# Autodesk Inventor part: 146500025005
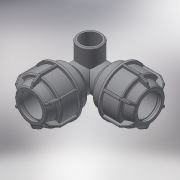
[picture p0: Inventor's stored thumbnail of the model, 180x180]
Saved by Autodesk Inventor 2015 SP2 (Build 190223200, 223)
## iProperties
Created: 2017-08
Part Number: 146500025005
Material: Generic
Description: PLASSON L.14 CORNER TEE ELBOW FEMALE (SILVER) 25-1/2"-25
Document SubType Name: Modeling
Designer: KIM
Density: 1 g/cm^3
Appearance: Default
Author: KIM
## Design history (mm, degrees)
derived "146500.ipt"
feature "Solid1::146500.ipt"
feature "Solid2::146500.ipt"
feature "Solid3::146500.ipt"
tag "TaggingFeature1"
body "Solid1"
body "Solid2"
body "Solid3"
other parameters: "d1" = 25, "d2" = 44, "d4" = 15 deg, "d5" = 29.04, "d6" = 9.5832, "d16" = 25.5, "d17" = 2.2, "d24" = 2.2, "d25" = 45, "d26" = 37.5, "d27" = 2.2, "d28" = 135 deg, "d29" = 1.32, "d31" = 1.25, "d46" = 150 deg, "d49" = 2.5, "d50" = 0, "d58" = 0.75, "d61" = 360 deg, "d63" = 17.69945, "d95" = 18.631, "d96" = 24.2203, "d97" = 17, "d98" = 13.97325, "d108" = 1.25, "d113" = 62, "d114" = 44.88, "d115" = 27.9465, "d116" = 45 deg, "d120" = 90 deg, "d123" = 0, "d124" = 0, "d125" = 4.47144, "d129" = 0, "d131" = 0, "d132" = 0, "d133" = 0, "d_" = 25, "G_" = 18.631, "A_" = 62, "l_" = 44, "l_2" = 17
